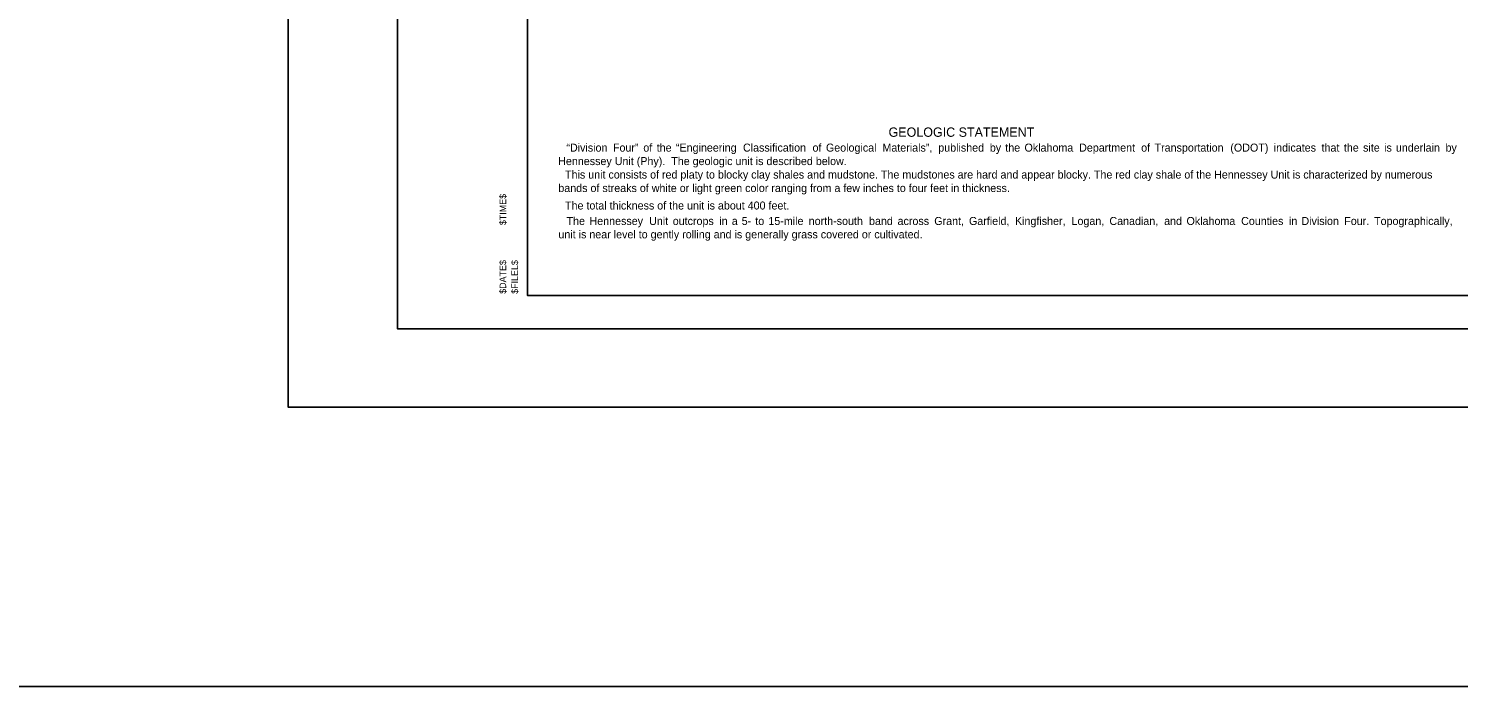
# Model space of a CAD drawing. Extents: x -6 to 173, y 24 to 64.
# Drawn here: x 86.09 to 107.52, y 25.78 to 35.65 of the extents above; entities that cross this region are included whole.
import ezdxf

# ---------------------------------------------------------------- set-up
doc = ezdxf.new("R2010")
doc.units = 0
for name, color, linetype in [('S', 7, 'Continuous'), ('SHT_Plot_Shape_Full', 7, 'Continuous'), ('SHT_Plot_Shape_Half', 7, 'Continuous'), ('SHT_Plot_Stamp', 7, 'Continuous'), ('SHT_Sheet_Border', 7, 'Continuous'), ('Text', 7, 'Continuous')]:
    doc.layers.add(name, color=color, linetype=linetype)

# ---------------------------------------------------------------- blocks, each defined once
blk = doc.blocks.new('Stamp_Plot_Stamp')
at = {"layer": 'SHT_Plot_Stamp'}
for s, p in [('$TIME$', (1.695, 1.572)), ('$DATE$', (1.695, 0.542)), ('$FILEL$', (1.873, 0.542))]:
    blk.add_text(s, height=0.1, rotation=90, dxfattribs=at).set_placement(p)

msp = doc.modelspace()

# ---------------------------------------------------------------- linework, layer by layer
at = {"layer": 'S'}
msp.add_lwpolyline([(-6.024, 64.421), (172.576, 64.421), (172.576, 25.783), (-6.024, 25.783)], close=True, dxfattribs=at)
at = {"layer": 'SHT_Plot_Shape_Full'}
msp.add_lwpolyline([(89.979, 53.971), (125.979, 53.971), (125.979, 29.971), (89.979, 29.971)], close=True, dxfattribs=at)
at = {"layer": 'SHT_Plot_Shape_Half'}
msp.add_lwpolyline([(91.616, 53.146), (125.616, 53.146), (125.616, 31.146), (91.616, 31.146)], close=True, dxfattribs=at)
at = {"layer": 'SHT_Sheet_Border'}
msp.add_lwpolyline([(93.566, 52.646), (125.066, 52.646), (125.066, 31.646), (93.566, 31.646)], close=True, dxfattribs=at)

# ---------------------------------------------------------------- block references
at = {"layer": 'SHT_Plot_Stamp'}
msp.add_blockref('Stamp_Plot_Stamp', (91.553, 31.127), dxfattribs=at)

# ---------------------------------------------------------------- texts
at = {"layer": 'Text'}
for s, height, p in [('GEOLOGIC STATEMENT', 0.14, (98.981, 34.023)), ('“Division', 0.12, (94.151, 33.801)), ('Four”', 0.12, (94.849, 33.801)), ('of', 0.12, (95.304, 33.801)), ('the', 0.12, (95.505, 33.801)), ('“Engineering', 0.12, (95.793, 33.801)), ('Classification', 0.12, (96.798, 33.801)), ('of', 0.12, (97.841, 33.801)), ('Geological', 0.12, (98.042, 33.801)), ('Materials”,', 0.12, (98.889, 33.801)), ('published', 0.12, (99.726, 33.801)), ('by', 0.12, (100.499, 33.801)), ('the', 0.12, (100.731, 33.801)), ('Oklahoma', 0.12, (101.019, 33.801)), ('Department', 0.12, (101.838, 33.801)), ('of', 0.12, (102.768, 33.801)), ('Transportation', 0.12, (102.969, 33.801)), ('(ODOT)', 0.12, (104.105, 33.801)), ('indicates', 0.12, (104.756, 33.801)), ('that', 0.12, (105.472, 33.801)), ('the', 0.12, (105.807, 33.801)), ('site', 0.12, (106.095, 33.801)), ('is', 0.12, (106.411, 33.801)), ('underlain', 0.12, (106.587, 33.801)), ('by', 0.12, (107.331, 33.801)), ('Hennessey Unit (Phy).  The geologic unit is described below.', 0.12, (94.028, 33.599)), ('  This unit consists of red platy to blocky clay shales and mudstone. The mudstones are hard and appear blocky. The red clay shale of the Hennessey Unit is characterized by numerous ', 0.12, (94.041, 33.397)), ('bands of streaks of white or light green color ranging from a few inches to four feet in thickness.', 0.12, (94.03, 33.195)), ('  The total thickness of the unit is about 400 feet.', 0.12, (94.041, 32.933)), ('The', 0.12, (94.153, 32.701)), ('Hennessey', 0.12, (94.497, 32.701)), ('Unit', 0.12, (95.391, 32.701)), ('outcrops', 0.12, (95.745, 32.701)), ('in', 0.12, (96.444, 32.701)), ('5-', 0.12, (96.779, 32.701)), ('to', 0.12, (96.983, 32.701)), ('15-mile', 0.12, (97.179, 32.701)), ('north-south', 0.12, (97.784, 32.701)), ('band', 0.12, (98.688, 32.701)), ('Grant,', 0.12, (99.666, 32.701)), ('Garfield,', 0.12, (100.187, 32.701)), ('Kingfisher,', 0.12, (100.876, 32.701)), ('Logan,', 0.12, (101.724, 32.701)), ('Canadian,', 0.12, (102.292, 32.701)), ('and', 0.12, (103.112, 32.701)), ('Oklahoma', 0.12, (103.448, 32.701)), ('Counties', 0.12, (104.267, 32.701)), ('in', 0.12, (104.985, 32.701)), ('Division', 0.12, (105.171, 32.701)), ('Four.', 0.12, (105.813, 32.701)), ('Topographically,', 0.12, (106.26, 32.701)), ('unit is near level to gently rolling and is generally grass covered or cultivated.  ', 0.12, (94.031, 32.501)), ('a', 0.12, (96.63, 32.701)), ('across', 0.12, (99.116, 32.701))]:
    msp.add_text(s, height=height, dxfattribs=at).set_placement(p)

doc.saveas('drawing.dxf')
